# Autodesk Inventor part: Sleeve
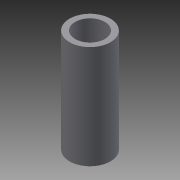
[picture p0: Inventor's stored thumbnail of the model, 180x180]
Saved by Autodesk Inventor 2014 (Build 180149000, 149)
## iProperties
Created: 2004-07
Part Number: Sleeve
Document SubType Name: Modeling
Designer: Autodesk, Inc.
Manufacturer: Standard
Standards Organization: Custom
Density: 1 g/cm^3
Mass: 9.93843 g
Surface Area: 69.8376 cm^2
Volume: 9.93843 cm^3
Material: Generic
Appearance: Default
Author: Autodesk, Inc.
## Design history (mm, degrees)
sketch "Sketch1"
  geometry: C1 r 11 at (0, 0); C2 r 8 at (0, 0); 1 further point
  constraints: 2 centre point, 2 coincident
  dimensions: "d0" = 22 diameter of C1; "d1" = 16 diameter of C2
extrude "Extrusion1" new body sketch "Sketch1" distance "d2" = 55.5; taper "d3" = 0 deg
body "Solid1"
